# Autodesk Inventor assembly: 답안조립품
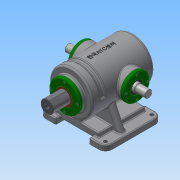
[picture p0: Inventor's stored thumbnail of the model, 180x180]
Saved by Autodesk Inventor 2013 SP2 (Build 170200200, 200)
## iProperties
Created: 2018-06
Part Number: 답안조립품
Document SubType Name: Assembly
Designer: Administrator
Author: Administrator
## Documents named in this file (13)
- C:\Users\Administrator\Desktop\380628V1011\답안조립품.iam
- C:\Users\Administrator\Desktop\380628V1011\본체.ipt
- C:\Users\Administrator\Desktop\380628V1011\가변스프링.ipt
- C:\Users\Administrator\Desktop\380628V1011\베어링 6205.ipt
- 베어링 6205.ipt
- C:\Users\Administrator\Desktop\380628V1011\볼트 M4.ipt
- C:\Users\Administrator\Desktop\380628V1011\부시.ipt
- C:\Users\Administrator\Desktop\380628V1011\슬라이드 커버.ipt
- C:\Users\Administrator\Desktop\380628V1011\슬라이드.ipt
- C:\Users\Administrator\Desktop\380628V1011\오일실.ipt
- 오일실.ipt
- C:\Users\Administrator\Desktop\380628V1011\축 커버.ipt
- C:\Users\Administrator\Desktop\380628V1011\편심축.ipt
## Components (1 placed, 1 different names)
1. 가변스프링:1
